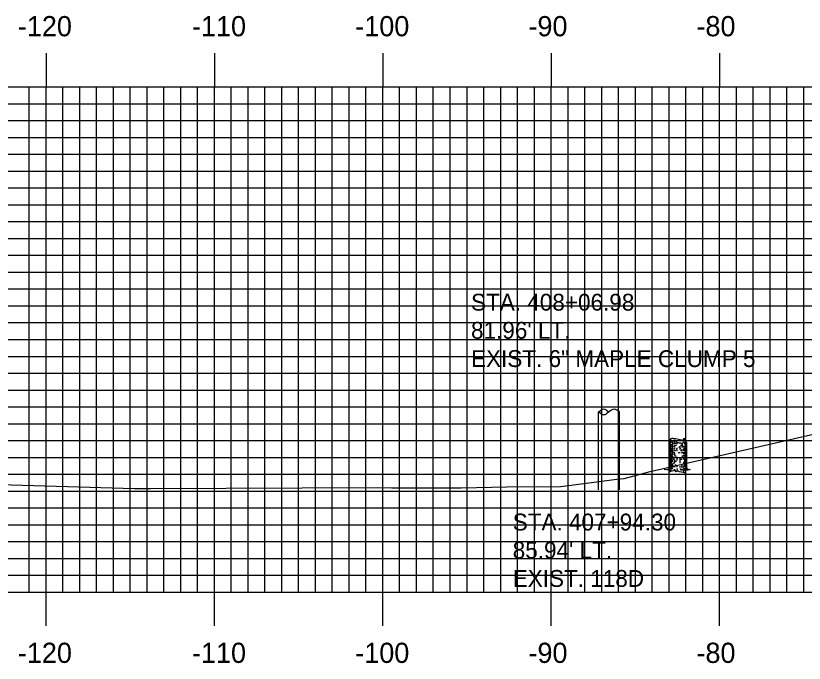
# Model space of a CAD drawing. Extents: x 852529 to 852872, y 364785 to 365005.
# Drawn here: x 852572.93 to 852619.76, y 364902.02 to 364940.45 of the extents above; entities that cross this region are included whole.
import ezdxf

# ---------------------------------------------------------------- set-up
doc = ezdxf.new("R2010")
doc.units = 0
for name, color, linetype in [('D_Text_Monospaced', 7, 'Continuous'), ('H_V ANNOTATION', 7, 'Continuous'), ('MAJOR', 7, 'Continuous'), ('MINOR', 7, 'Continuous'), ('S_Roadway_Centerline', 7, 'Continuous'), ('S_Trees_Decid_NonPay', 7, 'Continuous'), ('S_Utilities_Pole_Power', 7, 'Continuous')]:
    doc.layers.add(name, color=color, linetype=linetype)

msp = doc.modelspace()

# ---------------------------------------------------------------- linework, layer by layer
at = {"layer": 'MAJOR'}
for p, q in [((852574.731, 364938.237), (852574.731, 364936.233)), ((852584.731, 364938.237), (852584.731, 364936.233)), ((852594.731, 364938.237), (852594.731, 364936.233)), ((852604.731, 364938.237), (852604.731, 364936.233)), ((852614.731, 364938.237), (852614.731, 364936.233)), ((852554.731, 364936.233), (852834.731, 364936.233)), ((852554.731, 364936.233), (852834.731, 364936.233)), ((852574.731, 364906.233), (852574.731, 364936.233)), ((852584.731, 364906.233), (852584.731, 364936.233)), ((852594.731, 364906.233), (852594.731, 364936.233)), ((852604.731, 364906.233), (852604.731, 364936.233)), ((852614.731, 364906.233), (852614.731, 364936.233)), ((852554.731, 364931.233), (852834.731, 364931.233)), ((852554.731, 364926.233), (852834.731, 364926.233)), ((852554.731, 364921.233), (852834.731, 364921.233)), ((852554.731, 364916.233), (852834.731, 364916.233)), ((852554.731, 364911.233), (852834.731, 364911.233)), ((852554.731, 364906.233), (852834.731, 364906.233)), ((852554.731, 364906.233), (852834.731, 364906.233)), ((852574.731, 364904.229), (852574.731, 364906.233)), ((852584.731, 364904.229), (852584.731, 364906.233)), ((852594.731, 364904.229), (852594.731, 364906.233)), ((852604.731, 364904.229), (852604.731, 364906.233)), ((852614.731, 364904.229), (852614.731, 364906.233))]:
    msp.add_line(p, q, dxfattribs=at)
at = {"layer": 'MINOR'}
for p, q in [((852573.731, 364906.233), (852573.731, 364936.233)), ((852575.731, 364906.233), (852575.731, 364936.233)), ((852576.731, 364906.233), (852576.731, 364936.233)), ((852577.731, 364906.233), (852577.731, 364936.233)), ((852578.731, 364906.233), (852578.731, 364936.233)), ((852579.731, 364906.233), (852579.731, 364936.233)), ((852580.731, 364906.233), (852580.731, 364936.233)), ((852581.731, 364906.233), (852581.731, 364936.233)), ((852582.731, 364906.233), (852582.731, 364936.233)), ((852583.731, 364906.233), (852583.731, 364936.233)), ((852585.731, 364906.233), (852585.731, 364936.233)), ((852586.731, 364906.233), (852586.731, 364936.233)), ((852587.731, 364906.233), (852587.731, 364936.233)), ((852588.731, 364906.233), (852588.731, 364936.233)), ((852589.731, 364906.233), (852589.731, 364936.233)), ((852590.731, 364906.233), (852590.731, 364936.233)), ((852591.731, 364906.233), (852591.731, 364936.233)), ((852592.731, 364906.233), (852592.731, 364936.233)), ((852593.731, 364906.233), (852593.731, 364936.233)), ((852595.731, 364906.233), (852595.731, 364936.233)), ((852596.731, 364906.233), (852596.731, 364936.233)), ((852597.731, 364906.233), (852597.731, 364936.233)), ((852598.731, 364906.233), (852598.731, 364936.233)), ((852599.731, 364906.233), (852599.731, 364936.233)), ((852600.731, 364906.233), (852600.731, 364936.233)), ((852601.731, 364906.233), (852601.731, 364936.233)), ((852602.731, 364906.233), (852602.731, 364936.233)), ((852603.731, 364906.233), (852603.731, 364936.233)), ((852605.731, 364906.233), (852605.731, 364936.233)), ((852606.731, 364906.233), (852606.731, 364936.233)), ((852607.731, 364906.233), (852607.731, 364936.233)), ((852608.731, 364906.233), (852608.731, 364936.233)), ((852609.731, 364906.233), (852609.731, 364936.233)), ((852610.731, 364906.233), (852610.731, 364936.233)), ((852611.731, 364906.233), (852611.731, 364936.233)), ((852612.731, 364906.233), (852612.731, 364936.233)), ((852613.731, 364906.233), (852613.731, 364936.233)), ((852615.731, 364906.233), (852615.731, 364936.233)), ((852616.731, 364906.233), (852616.731, 364936.233)), ((852617.731, 364906.233), (852617.731, 364936.233)), ((852618.731, 364906.233), (852618.731, 364936.233)), ((852619.731, 364906.233), (852619.731, 364936.233)), ((852554.731, 364935.233), (852834.731, 364935.233)), ((852554.731, 364934.233), (852834.731, 364934.233)), ((852554.731, 364933.233), (852834.731, 364933.233)), ((852554.731, 364932.233), (852834.731, 364932.233)), ((852554.731, 364930.233), (852834.731, 364930.233)), ((852554.731, 364929.233), (852834.731, 364929.233)), ((852554.731, 364928.233), (852834.731, 364928.233)), ((852554.731, 364927.233), (852834.731, 364927.233)), ((852554.731, 364925.233), (852834.731, 364925.233)), ((852554.731, 364924.233), (852834.731, 364924.233)), ((852554.731, 364923.233), (852834.731, 364923.233)), ((852554.731, 364922.233), (852834.731, 364922.233)), ((852554.731, 364920.233), (852834.731, 364920.233)), ((852554.731, 364919.233), (852834.731, 364919.233)), ((852554.731, 364918.233), (852834.731, 364918.233)), ((852554.731, 364917.233), (852834.731, 364917.233)), ((852554.731, 364915.233), (852834.731, 364915.233)), ((852554.731, 364914.233), (852834.731, 364914.233)), ((852554.731, 364913.233), (852834.731, 364913.233)), ((852554.731, 364912.233), (852834.731, 364912.233)), ((852554.731, 364910.233), (852834.731, 364910.233)), ((852554.731, 364909.233), (852834.731, 364909.233)), ((852554.731, 364908.233), (852834.731, 364908.233)), ((852554.731, 364907.233), (852834.731, 364907.233))]:
    msp.add_line(p, q, dxfattribs=at)
at = {"layer": 'S_Roadway_Centerline'}
msp.add_lwpolyline([(852554.731, 364912.608), (852556.867, 364912.747), (852561.877, 364912.743), (852567.317, 364912.767), (852579.975, 364912.389), (852580.113, 364912.383), (852580.931, 364912.389), (852594.428, 364912.451), (852595.268, 364912.427), (852599.382, 364912.425), (852602.093, 364912.479), (852605.312, 364912.513), (852608.626, 364912.935), (852609.06, 364912.976), (852610.613, 364913.393), (852623.858, 364916.427)], dxfattribs=at)
at = {"layer": 'S_Trees_Decid_NonPay'}
for p, q in [((852611.867, 364915.252), (852611.867, 364915.157)), ((852611.867, 364914.931), (852611.867, 364914.848)), ((852611.935, 364915.165), (852611.935, 364914.864)), ((852611.935, 364914.836), (852611.935, 364914.704)), ((852612.054, 364915.182), (852612.054, 364915.034)), ((852612.054, 364914.986), (852612.054, 364914.817)), ((852612.201, 364915.136), (852612.201, 364915.029)), ((852612.381, 364914.9), (852612.381, 364914.7)), ((852612.498, 364915.084), (852612.498, 364915.005)), ((852612.498, 364914.918), (852612.498, 364914.834)), ((852612.585, 364914.9), (852612.585, 364914.813)), ((852612.656, 364915.073), (852612.656, 364915.021)), ((852612.656, 364914.918), (852612.656, 364914.836)), ((852612.698, 364915.078), (852612.698, 364914.861)), ((852612.725, 364915.008), (852612.725, 364914.926)), ((852612.725, 364914.857), (852612.725, 364914.727)), ((852611.867, 364914.778), (852611.867, 364914.527)), ((852611.867, 364914.445), (852611.867, 364914.214)), ((852611.935, 364914.67), (852611.935, 364914.389)), ((852612.054, 364914.511), (852612.054, 364914.362)), ((852612.201, 364914.801), (852612.201, 364914.714)), ((852612.201, 364914.679), (852612.201, 364914.609)), ((852612.498, 364914.723), (852612.498, 364914.622)), ((852612.498, 364914.537), (852612.498, 364914.461)), ((852612.585, 364914.743), (852612.585, 364914.622)), ((852612.585, 364914.546), (852612.585, 364914.432)), ((852612.585, 364914.37), (852612.585, 364914.288)), ((852612.656, 364914.801), (852612.656, 364914.727)), ((852612.656, 364914.7), (852612.656, 364914.64)), ((852612.656, 364914.587), (852612.656, 364914.406)), ((852612.656, 364914.374), (852612.656, 364914.292)), ((852612.698, 364914.792), (852612.698, 364914.64)), ((852612.698, 364914.535), (852612.698, 364914.457)), ((852612.698, 364914.43), (852612.698, 364914.323)), ((852612.725, 364914.704), (852612.725, 364914.523)), ((852612.725, 364914.475), (852612.725, 364914.229)), ((852611.867, 364914.144), (852611.867, 364913.983)), ((852611.867, 364913.967), (852611.867, 364913.862)), ((852611.935, 364914.319), (852611.935, 364914.175)), ((852611.935, 364914.105), (852611.935, 364913.963)), ((852612.054, 364914.093), (852612.054, 364913.94)), ((852612.201, 364914.276), (852612.201, 364914.053)), ((852612.381, 364914.162), (852612.381, 364913.975)), ((852612.381, 364913.945), (852612.381, 364913.891)), ((852612.498, 364914.276), (852612.498, 364914.179)), ((852612.585, 364914.202), (852612.585, 364914.105)), ((852612.585, 364913.975), (852612.585, 364913.876)), ((852612.656, 364914.238), (852612.656, 364914.068)), ((852612.656, 364914.034), (852612.656, 364913.755)), ((852612.698, 364914.288), (852612.698, 364914.187)), ((852612.698, 364914.162), (852612.698, 364913.979)), ((852612.725, 364914.21), (852612.725, 364914.115)), ((852612.727, 364914.062), (852612.726, 364913.802)), ((852611.867, 364913.825), (852611.867, 364913.701)), ((852611.934, 364913.621), (852611.893, 364913.525)), ((852611.935, 364913.862), (852611.935, 364913.681)), ((852612.054, 364913.728), (852612.054, 364913.65)), ((852612.201, 364913.72), (852612.201, 364913.654)), ((852612.241, 364913.434), (852612.206, 364913.58)), ((852612.381, 364913.716), (852612.381, 364913.625)), ((852612.498, 364913.854), (852612.498, 364913.63)), ((852612.585, 364913.747), (852612.585, 364913.689)), ((852612.656, 364913.702), (852612.656, 364913.677)), ((852612.696, 364913.637), (852612.731, 364913.586)), ((852612.698, 364913.876), (852612.698, 364913.685)), ((852612.778, 364913.516), (852612.711, 364913.547)), ((852612.725, 364913.763), (852612.725, 364913.689))]:
    msp.add_line(p, q, dxfattribs=at)
for points in [[(852612.766, 364915.116), (852612.766, 364913.704), (852612.789, 364913.555), (852612.992, 364913.512), (852612.852, 364913.477), (852612.634, 364913.458), (852612.564, 364913.415), (852612.686, 364913.326), (852612.354, 364913.37), (852612.241, 364913.434), (852612.148, 364913.374), (852612.093, 364913.452), (852612.101, 364913.489), (852612.039, 364913.491), (852611.988, 364913.434), (852611.755, 364913.382), (852611.883, 364913.471), (852611.751, 364913.473), (852611.442, 364913.51), (852611.681, 364913.541), (852611.759, 364913.599), (852611.798, 364913.72), (852611.815, 364914.074), (852611.815, 364915.307)], [(852612.671, 364915.196), (852612.667, 364915.291), (852612.653, 364915.264), (852612.653, 364915.385), (852612.632, 364915.322), (852612.617, 364915.355), (852612.601, 364915.299), (852612.585, 364915.316), (852612.566, 364915.307), (852612.547, 364915.24)], [(852612.179, 364915.141), (852612.171, 364915.208), (852612.146, 364915.213), (852612.138, 364915.248), (852612.107, 364915.233), (852612.093, 364915.248), (852612.068, 364915.225), (852612.045, 364915.233), (852612.033, 364915.282), (852612.025, 364915.239), (852611.994, 364915.248), (852611.991, 364915.196)], [(852612.649, 364915.072), (852612.632, 364915.134), (852612.61, 364915.122), (852612.579, 364915.157), (852612.545, 364915.079)], [(852611.864, 364913.658), (852611.856, 364913.582), (852611.778, 364913.532)], [(852612.389, 364913.576), (852612.389, 364913.539), (852612.44, 364913.508), (852612.457, 364913.458)], [(852612.501, 364913.582), (852612.507, 364913.512), (852612.57, 364913.5)], [(852612.648, 364913.547), (852612.605, 364913.582), (852612.597, 364913.63)], [(852612.727, 364913.563), (852612.648, 364913.547), (852612.632, 364913.504)]]:
    msp.add_lwpolyline(points, dxfattribs=at)
for centre, radius, start, end in [((852611.833, 364915.307), 0.0179, 168.1723, 184.2278), ((852611.839, 364915.308), 0.0237, 184.2278, 198.1723), ((852611.833, 364915.307), 0.0179, 152.1168, 168.1723), ((852611.848, 364915.311), 0.0336, 198.1723, 216.9486), ((852611.838, 364915.305), 0.0237, 138.1723, 152.1168), ((852611.846, 364915.298), 0.0336, 119.396, 138.1723), ((852611.875, 364915.246), 0.0935, 108.1723, 119.396), ((852611.946, 364915.029), 0.322, 86.0543, 108.1723), ((852611.796, 364912.849), 2.507, 78.1723, 86.0543), ((852611.796, 364912.849), 2.507, 70.2902, 78.1723), ((852611.834, 364915.16), 0.0191, 163.9485, 180), ((852611.834, 364915.16), 0.0191, 180, 196.0515), ((852611.84, 364915.162), 0.0252, 196.0515, 210), ((852611.834, 364914.946), 0.0191, 163.9485, 180), ((852611.834, 364914.946), 0.0191, 180, 196.0515), ((852611.84, 364914.948), 0.0252, 196.0515, 210), ((852611.834, 364914.843), 0.0191, 163.9485, 180), ((852611.834, 364914.843), 0.0191, 180, 196.0515), ((852611.84, 364914.845), 0.0252, 196.0515, 210), ((852611.849, 364915.167), 0.0356, 210, 228.7494), ((852611.849, 364914.953), 0.0356, 210, 228.7494), ((852611.849, 364914.85), 0.0356, 210, 228.7494), ((852611.896, 364915.347), 0.0935, 216.9486, 228.1723), ((852611.89, 364915.214), 0.0984, 228.7494, 240), ((852611.89, 364915), 0.0984, 228.7494, 240), ((852611.89, 364914.897), 0.0984, 228.7494, 240), ((852612.049, 364915.517), 0.322, 228.1723, 250.2902), ((852612.004, 364915.411), 0.326, 240, 248.3243), ((852612.004, 364915.197), 0.326, 240, 243.5719), ((852612.004, 364915.298), 0.326, 240.9099, 257.8036), ((852612.004, 364915.197), 0.326, 250.4167, 261.8968), ((852612.004, 364915.411), 0.326, 257.8036, 261.8968), ((852612.785, 364917.574), 2.507, 250.2902, 251.5281), ((852612.29, 364917.421), 2.356, 261.8968, 263.2799), ((852612.29, 364917.207), 2.356, 261.8968, 262.5519), ((852612.29, 364917.308), 2.356, 264.242, 267.3673), ((852612.29, 364917.421), 2.356, 265.24, 267.8386), ((852612.785, 364917.574), 2.507, 255.9987, 258.1723), ((852612.785, 364917.574), 2.507, 258.1723, 264.5013), ((852612.29, 364917.207), 2.356, 270.8119, 272.1981), ((852612.29, 364917.308), 2.356, 273.1481, 276.7734), ((852612.29, 364917.207), 2.356, 275.0647, 278.1032), ((852612.576, 364915.197), 0.326, 278.1032, 279.0854), ((852612.533, 364914.906), 0.322, 48.1723, 70.2902), ((852612.635, 364915.394), 0.322, 272.4479, 288.1723), ((852612.576, 364915.298), 0.326, 291.9506, 300), ((852612.576, 364915.197), 0.326, 291.9506, 300), ((852612.706, 364915.177), 0.0935, 288.1723, 299.396), ((852612.69, 364915.101), 0.0984, 300, 311.2506), ((852612.69, 364915), 0.0984, 300, 311.2506), ((852612.685, 364915.076), 0.0935, 36.9486, 48.1723), ((852612.736, 364915.125), 0.0336, 299.396, 318.1723), ((852612.731, 364915.054), 0.0356, 311.2506, 330), ((852612.731, 364914.953), 0.0356, 311.2506, 330), ((852612.733, 364915.112), 0.0336, 18.1723, 36.9486), ((852612.743, 364915.119), 0.0237, 318.1723, 332.1168), ((852612.74, 364915.048), 0.0252, 330, 343.9485), ((852612.74, 364914.948), 0.0252, 330, 343.9485), ((852612.748, 364915.116), 0.0179, 332.1168, 348.1723), ((852612.742, 364915.115), 0.0237, 4.2278, 18.1723), ((852612.746, 364915.047), 0.0191, 360, 6.1128), ((852612.746, 364915.047), 0.0191, 343.9485, 360), ((852612.746, 364914.946), 0.0191, 360, 6.1128), ((852612.746, 364914.946), 0.0191, 343.9485, 360), ((852612.746, 364914.843), 0.0191, 360, 6.1128), ((852612.746, 364914.843), 0.0191, 343.9485, 360), ((852612.748, 364915.116), 0.0179, 348.1723, 4.2278), ((852611.831, 364914.408), 0.0191, 163.9485, 180), ((852611.834, 364914.623), 0.0191, 163.9485, 180), ((852611.834, 364914.623), 0.0191, 180, 196.0515), ((852611.84, 364914.625), 0.0252, 196.0515, 210), ((852611.834, 364914.508), 0.0191, 163.9485, 180), ((852611.834, 364914.508), 0.0191, 180, 196.0515), ((852611.84, 364914.51), 0.0252, 196.0515, 210), ((852611.849, 364914.63), 0.0356, 210, 228.7494), ((852611.849, 364914.515), 0.0356, 210, 228.7494), ((852611.89, 364914.677), 0.0984, 228.7494, 240), ((852611.891, 364914.563), 0.0984, 228.7494, 240), ((852612.001, 364914.66), 0.326, 240, 256.9079), ((852612.004, 364915.094), 0.326, 240, 243.243), ((852612.004, 364914.874), 0.326, 240, 245.1545), ((852612.005, 364914.76), 0.326, 240, 247.8656), ((852612.004, 364914.989), 0.326, 245.1545, 257.8036), ((852612.004, 364915.094), 0.326, 251.6831, 257.8036), ((852612.005, 364914.76), 0.326, 257.6699, 261.8968), ((852612.291, 364916.77), 2.356, 261.8968, 262.8615), ((852612.29, 364916.884), 2.356, 262.6588, 264.7911), ((852612.29, 364916.999), 2.356, 263.2682, 265.6362), ((852612.29, 364917.104), 2.356, 263.3413, 264.9946), ((852612.29, 364917.104), 2.356, 266.5036, 267.8386), ((852612.29, 364916.884), 2.356, 269.5578, 270), ((852612.29, 364916.884), 2.356, 270, 272.414), ((852612.29, 364917.104), 2.356, 272.1981, 273.9741), ((852612.29, 364916.999), 2.356, 273.0067, 275.0647), ((852612.29, 364916.884), 2.356, 275.0647, 277.1868), ((852612.29, 364916.999), 2.356, 277.1868, 278.1032), ((852612.29, 364917.104), 2.356, 277.3838, 278.1032), ((852612.576, 364915.094), 0.326, 278.1032, 284.0382), ((852612.576, 364914.989), 0.326, 278.1032, 284.0382), ((852612.576, 364914.874), 0.326, 284.0382, 300), ((852612.577, 364914.76), 0.326, 283.9036, 291.8098), ((852612.576, 364914.989), 0.326, 291.9506, 300), ((852612.574, 364914.66), 0.326, 292.4049, 300), ((852612.577, 364914.76), 0.326, 297.0058, 300), ((852612.688, 364914.462), 0.0984, 300, 311.2506), ((852612.69, 364914.792), 0.0984, 300, 311.2506), ((852612.69, 364914.677), 0.0984, 300, 311.2506), ((852612.691, 364914.563), 0.0984, 300, 311.2506), ((852612.729, 364914.415), 0.0356, 311.2506, 330), ((852612.731, 364914.745), 0.0356, 311.2506, 330), ((852612.731, 364914.63), 0.0356, 311.2506, 330), ((852612.732, 364914.515), 0.0356, 311.2506, 330), ((852612.738, 364914.41), 0.0252, 330, 343.9485), ((852612.74, 364914.74), 0.0252, 330, 343.9485), ((852612.74, 364914.625), 0.0252, 330, 343.9485), ((852612.744, 364914.408), 0.0191, 343.9485, 360), ((852612.741, 364914.51), 0.0252, 330, 343.9485), ((852612.744, 364914.408), 0.0191, 0, 6.1128), ((852612.746, 364914.738), 0.0191, 360, 6.1128), ((852612.746, 364914.738), 0.0191, 343.9485, 360), ((852612.746, 364914.623), 0.0191, 360, 6.1128), ((852612.746, 364914.623), 0.0191, 343.9485, 360), ((852612.747, 364914.508), 0.0191, 343.9485, 360), ((852612.747, 364914.508), 0.0191, 0, 6.1128), ((852611.83, 364913.984), 0.0191, 163.9485, 180), ((852611.83, 364913.984), 0.0191, 180, 196.0515), ((852611.835, 364913.986), 0.0252, 196.0515, 210), ((852611.844, 364913.991), 0.0356, 210, 228.7494), ((852611.834, 364914.303), 0.0191, 163.9485, 180), ((852611.834, 364914.303), 0.0191, 180, 196.0515), ((852611.84, 364914.305), 0.0252, 196.0515, 210), ((852611.849, 364914.31), 0.0356, 210, 228.7494), ((852611.886, 364914.039), 0.0984, 228.7494, 240), ((852611.89, 364914.358), 0.0984, 228.7494, 240), ((852612, 364914.236), 0.326, 240, 245.9375), ((852612.004, 364914.555), 0.326, 240, 245.1545), ((852612.004, 364914.464), 0.326, 241.939, 253.9183), ((852612.286, 364916.246), 2.356, 262.2226, 264.4852), ((852612.29, 364916.474), 2.356, 262.5843, 264.4865), ((852612.29, 364916.361), 2.356, 264.242, 267.469), ((852612.288, 364916.67), 2.356, 264.3443, 266.8529), ((852612.29, 364916.565), 2.356, 267.8386, 269.0054), ((852612.29, 364916.474), 2.356, 272.1981, 275.2726), ((852612.288, 364916.67), 2.356, 274.9734, 277.2455), ((852612.29, 364916.565), 2.356, 275.0647, 276.428), ((852612.286, 364916.246), 2.356, 277.2863, 278.1032), ((852612.572, 364914.236), 0.326, 278.1032, 284.7741), ((852612.576, 364914.555), 0.326, 284.0382, 291.9506), ((852612.576, 364914.351), 0.326, 284.0382, 291.9506), ((852612.576, 364914.555), 0.326, 297.1525, 300), ((852612.686, 364914.039), 0.0984, 300, 311.2506), ((852612.69, 364914.358), 0.0984, 300, 311.2506), ((852612.727, 364913.991), 0.0356, 311.2506, 330), ((852612.731, 364914.31), 0.0356, 311.2506, 330), ((852612.736, 364913.986), 0.0252, 330, 343.9485), ((852612.742, 364913.984), 0.0191, 360, 6.1128), ((852612.742, 364913.984), 0.0191, 343.9485, 360), ((852612.74, 364914.305), 0.0252, 330, 343.9485), ((852612.746, 364914.303), 0.0191, 360, 6.1128), ((852612.746, 364914.303), 0.0191, 343.9485, 360), ((852612.746, 364914.213), 0.0191, 360, 6.1128), ((852611.819, 364913.764), 0.0191, 163.9485, 180), ((852611.819, 364913.764), 0.0191, 180, 196.0515), ((852611.825, 364913.765), 0.0252, 196.0515, 210), ((852611.834, 364913.77), 0.0356, 210, 228.7494), ((852611.825, 364913.874), 0.0191, 163.9485, 180), ((852611.825, 364913.874), 0.0191, 180, 196.0515), ((852611.831, 364913.876), 0.0252, 196.0515, 210), ((852611.84, 364913.881), 0.0356, 210, 228.7494), ((852611.876, 364913.818), 0.0984, 228.7494, 240), ((852611.881, 364913.928), 0.0984, 228.7494, 240), ((852611.989, 364914.015), 0.326, 240, 247.9161), ((852611.995, 364914.125), 0.326, 240, 241.9097), ((852611.989, 364914.015), 0.326, 260.3834, 261.8968), ((852612.276, 364916.025), 2.356, 261.8968, 263.5333), ((852612.281, 364916.135), 2.356, 264.9089, 266.8158), ((852612.281, 364916.135), 2.356, 274.1864, 275.2829), ((852612.276, 364916.025), 2.356, 274.5551, 275.4167), ((852612.276, 364916.025), 2.356, 277.5403, 278.1032), ((852612.562, 364914.015), 0.326, 278.1032, 294.7094), ((852612.567, 364914.125), 0.326, 293.6544, 300), ((852612.676, 364913.818), 0.0984, 300, 311.2506), ((852612.717, 364913.77), 0.0356, 311.2506, 330), ((852612.726, 364913.765), 0.0252, 330, 343.9485), ((852612.732, 364913.764), 0.0191, 343.9485, 360), ((852612.732, 364913.764), 0.0191, 0, 6.1128)]:
    msp.add_arc(centre, radius, start, end, dxfattribs=at)
at = {"layer": 'S_Utilities_Pole_Power'}
for p, q in [((852607.539, 364916.932), (852607.695, 364917.043)), ((852607.539, 364912.313), (852607.542, 364916.932)), ((852607.695, 364916.821), (852607.539, 364916.932)), ((852608.008, 364917.043), (852608.164, 364916.932)), ((852608.164, 364916.932), (852608.008, 364916.821)), ((852608.32, 364917.043), (852608.164, 364916.932)), ((852608.789, 364916.932), (852608.633, 364917.043)), ((852608.789, 364912.313), (852608.792, 364916.932))]:
    msp.add_line(p, q, dxfattribs=at)
for centre, start, end in [((852607.852, 364916.822), 90, 125.2644), ((852607.852, 364917.043), 234.7356, 270), ((852607.852, 364916.822), 54.7356, 90), ((852607.852, 364917.043), 270, 305.2644), ((852608.477, 364916.822), 90, 125.2644), ((852608.477, 364916.822), 54.7356, 90)]:
    msp.add_arc(centre, 0.271, start, end, dxfattribs=at)

# ---------------------------------------------------------------- texts
at = {"layer": 'D_Text_Monospaced'}
for s, height, p in [('STA. 408+06.98', 0.99996, (852599.97, 364922.947)), ("81.96' LT.", 1, (852599.97, 364921.279)), ('EXIST. 6" MAPLE CLUMP 5', 0.99996, (852599.97, 364919.599)), ('STA. 407+94.30', 0.99996, (852602.447, 364909.896)), ("85.94' LT.", 1, (852602.447, 364908.228)), ('EXIST. 118D', 0.99996, (852602.447, 364906.548))]:
    msp.add_text(s, height=height, dxfattribs=at).set_placement(p)
at = {"layer": 'H_V ANNOTATION'}
for s, p in [('-120', (852573.05, 364939.233)), ('-110', (852583.393, 364939.233)), ('-100', (852593.093, 364939.233)), ('-90', (852603.382, 364939.233)), ('-80', (852613.361, 364939.233)), ('-120', (852573.05, 364902.033)), ('-110', (852583.393, 364902.033)), ('-100', (852593.093, 364902.033)), ('-90', (852603.382, 364902.033)), ('-80', (852613.361, 364902.033))]:
    msp.add_text(s, height=1.2, dxfattribs=at).set_placement(p)

doc.saveas('drawing.dxf')
